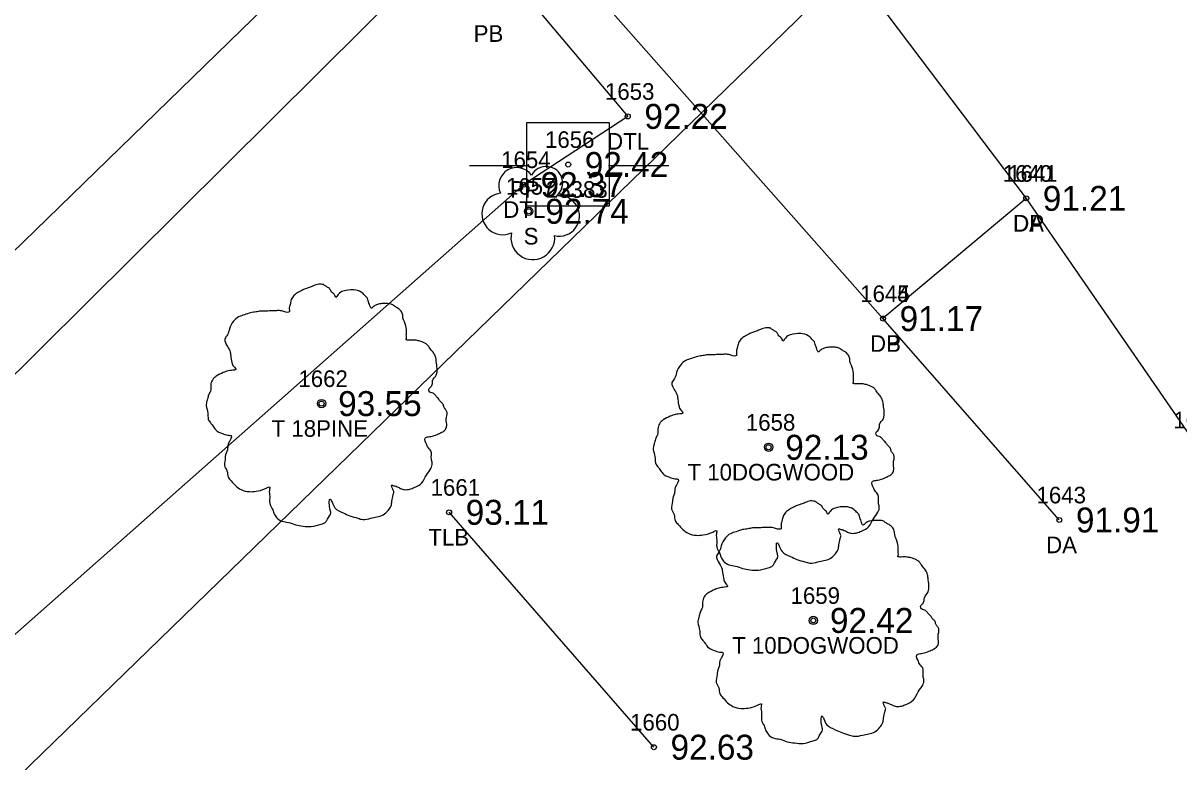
# Model space of a CAD drawing. Extents: x 2500794 to 2511032, y 910653 to 917533.
# Drawn here: x 2504774.7 to 2504844.2, y 912430.5 to 912475 of the extents above; entities that cross this region are included whole.
import ezdxf

# ---------------------------------------------------------------- set-up
doc = ezdxf.new("R2010")
doc.units = 0
for name, color, linetype in [('RD_EX_DR_Pipe_txCode', 7, 'Continuous'), ('RD_EX_Driveway', 7, 'Continuous'), ('RD_EX_Driveway_txCode', 7, 'Continuous'), ('RD_EX_H2O_txCode', 7, 'Continuous'), ('RD_EX_Road', 7, 'Continuous'), ('RD_EX_RW', 7, 'Continuous'), ('RD_EX_TX_Driveway_ELEV', 7, 'Continuous'), ('RD_EX_TX_H2O_ELEV', 7, 'Continuous'), ('RD_EX_TX_VEG_ELEV', 7, 'Continuous'), ('RD_EX_UT', 7, 'Continuous'), ('RD_EX_UT_txCode', 7, 'Continuous'), ('RD_EX_VEG', 7, 'Continuous'), ('RD_EX_VEG_txCode', 7, 'Continuous'), ('RD_HC_Survey_ELEV', 7, 'Continuous'), ('RD_SMD_Locator', 7, 'Continuous')]:
    doc.layers.add(name, color=color, linetype=linetype)

msp = doc.modelspace()

# ---------------------------------------------------------------- linework, layer by layer
at = {"layer": 'RD_EX_Driveway'}
for p, q in [((2504835.044, 912464.414), (2504845.262, 912449.566)), ((2504837.037, 912445.051), (2504826.429, 912457.175))]:
    msp.add_line(p, q, dxfattribs=at)
msp.add_lwpolyline([(2504810.704, 912496.654), (2504835.044, 912464.414), (2504826.429, 912457.175), (2504806.818, 912479.369), (2504795.802, 912482.321)], dxfattribs=at)
at = {"layer": 'RD_EX_H2O_txCode'}
for points in [[(2504800.806, 912480.276), (2504750.663, 912430.459), (2504704.437, 912384.367), (2504708.299, 912378.983)], [(2504800.806, 912480.276), (2504804.552, 912477.095), (2504811.074, 912469.349), (2504804.829, 912465.241), (2504757.76, 912423.62), (2504708.299, 912378.983)]]:
    msp.add_lwpolyline(points, dxfattribs=at)
at = {"layer": 'RD_EX_Road'}
msp.add_lwpolyline([(2505370.603, 913041.775), (2505311.868, 912984.114), (2505268.008, 912941.433), (2505190.916, 912867.207), (2505116.283, 912794.427), (2505039.137, 912719.026), (2504973.125, 912654.769), (2504957.318, 912639.487), (2504897.436, 912581.224), (2504858.984, 912543.75), (2504838.286, 912523.698), (2504810.704, 912496.654), (2504795.802, 912482.321), (2504747.074, 912434.903), (2504696.605, 912386.172), (2504686.806, 912376.673), (2504668.39, 912358.371), (2504598.363, 912290.291), (2504547.084, 912240.341)], dxfattribs=at)
at = {"layer": 'RD_EX_RW'}
msp.add_line((2503981.182, 911658.034), (2505252.676, 912894.806), dxfattribs=at)
at = {"layer": 'RD_EX_UT'}
for p, q in [((2504809.981, 912468.96), (2504804.981, 912468.96)), ((2504804.981, 912468.96), (2504804.981, 912463.96)), ((2504809.981, 912463.96), (2504809.981, 912468.96)), ((2504801.55, 912466.398), (2504805.019, 912466.398)), ((2504809.91, 912466.398), (2504813.55, 912466.398)), ((2504804.981, 912463.96), (2504809.981, 912463.96))]:
    msp.add_line(p, q, dxfattribs=at)
at = {"layer": 'RD_EX_VEG'}
msp.add_line((2504812.648, 912431.372), (2504800.324, 912445.513), dxfattribs=at)
for centre, radius in [((2504805.118, 912463.636), 0.25), ((2504792.654, 912452.058), 0.25), ((2504792.642, 912452.039), 0.0001), ((2504819.549, 912449.429), 0.25), ((2504819.537, 912449.41), 0.0001), ((2504822.238, 912439.002), 0.25), ((2504822.226, 912438.983), 0.0001)]:
    msp.add_circle(centre, radius, dxfattribs=at)
for centre, radius, start, end in [((2504804.397, 912465.183), 1.084, 34.97629, 204.75602), ((2504806.164, 912465.338), 0.995, 308.76261, 152.04674), ((2504803.555, 912463.481), 1.257, 96.45179, 294.73401), ((2504806.958, 912463.357), 1.218, 256.56668, 98.10463), ((2504805.364, 912462.04), 1.318, 166.88266, 5.75893)]:
    msp.add_arc(centre, radius, start, end, dxfattribs=at)
for points in [[(2504792.786, 912459.225), (2504792.486, 912459.25), (2504792.162, 912459.15), (2504791.912, 912459.05), (2504791.687, 912458.975), (2504791.462, 912458.875), (2504791.162, 912458.701), (2504790.937, 912458.501), (2504790.812, 912458.251), (2504790.762, 912458.026), (2504790.712, 912457.751), (2504790.712, 912457.576), (2504790.587, 912457.551), (2504790.437, 912457.576), (2504790.187, 912457.651), (2504789.938, 912457.651), (2504789.688, 912457.651), (2504789.338, 912457.626), (2504788.988, 912457.626), (2504788.713, 912457.576), (2504788.388, 912457.526), (2504788.013, 912457.401), (2504787.664, 912457.276), (2504787.364, 912457.026), (2504787.114, 912456.551), (2504786.989, 912456.202), (2504786.839, 912455.952), (2504786.989, 912455.502), (2504787.164, 912455.152), (2504787.189, 912454.952), (2504787.264, 912454.527), (2504787.364, 912454.302), (2504787.489, 912454.102), (2504787.414, 912454.078), (2504787.039, 912454.028), (2504786.739, 912453.928), (2504786.314, 912453.703), (2504786.089, 912453.478), (2504785.989, 912453.153), (2504785.964, 912452.803), (2504785.864, 912452.603), (2504785.789, 912452.328), (2504785.764, 912452.253), (2504785.714, 912451.928), (2504785.814, 912451.479), (2504785.839, 912451.129), (2504785.964, 912450.904), (2504786.114, 912450.729), (2504786.289, 912450.479), (2504786.689, 912450.254), (2504787.014, 912450.154), (2504787.214, 912450.129), (2504787.039, 912449.629), (2504786.989, 912449.28), (2504786.864, 912448.88), (2504786.864, 912448.805), (2504786.814, 912448.33), (2504786.964, 912448.005), (2504787.039, 912447.63), (2504787.214, 912447.405), (2504787.489, 912447.106), (2504787.813, 912446.881), (2504788.313, 912446.756), (2504788.713, 912446.781), (2504789.288, 912446.956), (2504789.538, 912447.031), (2504789.513, 912446.856), (2504789.538, 912446.481), (2504789.538, 912446.056), (2504789.688, 912445.731), (2504789.788, 912445.456), (2504789.938, 912445.206), (2504790.262, 912444.982), (2504790.662, 912444.907), (2504791.087, 912444.757), (2504791.537, 912444.682), (2504792.037, 912444.657), (2504792.636, 912444.807), (2504792.911, 912444.932), (2504793.011, 912445.106), (2504793.211, 912445.481), (2504793.161, 912445.706), (2504793.186, 912446.306), (2504793.286, 912446.131), (2504793.461, 912445.781), (2504793.961, 912445.481), (2504794.361, 912445.306), (2504794.835, 912445.156), (2504795.135, 912445.081), (2504795.61, 912445.156), (2504795.985, 912445.231), (2504796.36, 912445.356), (2504796.66, 912445.631), (2504796.835, 912445.906), (2504796.885, 912446.181), (2504796.959, 912446.556), (2504797.009, 912446.731)], [(2504797.009, 912446.731), (2504796.935, 912446.906), (2504796.885, 912447.156), (2504796.959, 912447.131), (2504797.134, 912447.081), (2504797.409, 912446.956), (2504797.634, 912446.881), (2504797.959, 912446.906), (2504798.234, 912447.006), (2504798.684, 912447.281), (2504798.959, 912447.755), (2504799.233, 912448.155), (2504799.308, 912448.48), (2504799.258, 912448.705), (2504799.233, 912449.205), (2504799.034, 912449.455), (2504798.984, 912449.579), (2504798.884, 912449.979), (2504798.959, 912450.029), (2504799.233, 912450.079), (2504799.608, 912450.204), (2504799.883, 912450.329), (2504800.108, 912450.504), (2504800.183, 912450.729), (2504800.158, 912451.129), (2504800.208, 912451.529), (2504800.133, 912451.679), (2504800.033, 912451.828), (2504799.958, 912452.028), (2504799.808, 912452.178), (2504799.708, 912452.328), (2504799.608, 912452.428), (2504799.483, 912452.578), (2504799.308, 912452.703), (2504799.159, 912452.753), (2504799.109, 912452.903), (2504799.258, 912453.103), (2504799.308, 912453.203), (2504799.333, 912453.428), (2504799.558, 912453.778), (2504799.608, 912454.177), (2504799.558, 912454.602), (2504799.508, 912454.877), (2504799.358, 912455.152), (2504799.159, 912455.402), (2504799.034, 912455.577), (2504798.859, 912455.702), (2504798.534, 912455.827), (2504798.284, 912455.877), (2504797.934, 912455.877), (2504797.734, 912455.927), (2504797.759, 912455.977), (2504797.759, 912456.127), (2504797.759, 912456.402), (2504797.684, 912456.851), (2504797.534, 912457.351), (2504797.534, 912457.376), (2504797.434, 912457.626), (2504797.209, 912457.826), (2504797.034, 912457.926), (2504796.835, 912458.051), (2504796.585, 912458.076), (2504796.285, 912458.076), (2504796.01, 912458.026), (2504795.81, 912457.926), (2504795.635, 912457.801), (2504795.56, 912457.951), (2504795.46, 912458.251), (2504795.41, 912458.401), (2504795.26, 912458.576), (2504795.035, 912458.775), (2504794.585, 912458.9), (2504793.961, 912458.825), (2504793.661, 912458.626), (2504793.511, 912458.451), (2504793.461, 912458.576), (2504793.261, 912458.775), (2504793.161, 912458.95), (2504792.986, 912459.075), (2504792.836, 912459.175), (2504792.736, 912459.225)], [(2504819.681, 912456.597), (2504819.381, 912456.622), (2504819.057, 912456.522), (2504818.807, 912456.422), (2504818.582, 912456.347), (2504818.357, 912456.247), (2504818.057, 912456.072), (2504817.832, 912455.872), (2504817.707, 912455.622), (2504817.657, 912455.397), (2504817.607, 912455.122), (2504817.607, 912454.947), (2504817.482, 912454.922), (2504817.332, 912454.947), (2504817.082, 912455.022), (2504816.833, 912455.022), (2504816.583, 912455.022), (2504816.233, 912454.997), (2504815.883, 912454.997), (2504815.608, 912454.947), (2504815.283, 912454.897), (2504814.908, 912454.772), (2504814.559, 912454.647), (2504814.259, 912454.397), (2504814.009, 912453.923), (2504813.884, 912453.573), (2504813.734, 912453.323), (2504813.884, 912452.873), (2504814.059, 912452.523), (2504814.084, 912452.323), (2504814.159, 912451.899), (2504814.259, 912451.674), (2504814.384, 912451.474), (2504814.309, 912451.449), (2504813.934, 912451.399), (2504813.634, 912451.299), (2504813.209, 912451.074), (2504812.984, 912450.849), (2504812.884, 912450.524), (2504812.859, 912450.174), (2504812.759, 912449.974), (2504812.684, 912449.7), (2504812.659, 912449.625), (2504812.609, 912449.3), (2504812.709, 912448.85), (2504812.734, 912448.5), (2504812.859, 912448.275), (2504813.009, 912448.1), (2504813.184, 912447.85), (2504813.584, 912447.625), (2504813.909, 912447.525), (2504814.109, 912447.501), (2504813.934, 912447.001), (2504813.884, 912446.651), (2504813.759, 912446.251), (2504813.759, 912446.176), (2504813.709, 912445.701), (2504813.859, 912445.376), (2504813.934, 912445.002), (2504814.109, 912444.777), (2504814.384, 912444.477), (2504814.708, 912444.252), (2504815.208, 912444.127), (2504815.608, 912444.152), (2504816.183, 912444.327), (2504816.433, 912444.402), (2504816.408, 912444.227), (2504816.433, 912443.852), (2504816.433, 912443.427), (2504816.583, 912443.102), (2504816.683, 912442.828), (2504816.833, 912442.578), (2504817.157, 912442.353), (2504817.557, 912442.278), (2504817.982, 912442.128), (2504818.432, 912442.053), (2504818.932, 912442.028), (2504819.531, 912442.178), (2504819.806, 912442.303), (2504819.906, 912442.478), (2504820.106, 912442.853), (2504820.056, 912443.077), (2504820.081, 912443.677), (2504820.181, 912443.502), (2504820.356, 912443.152), (2504820.856, 912442.853), (2504821.256, 912442.678), (2504821.73, 912442.528), (2504822.03, 912442.453), (2504822.505, 912442.528), (2504822.88, 912442.603), (2504823.255, 912442.728), (2504823.555, 912443.002), (2504823.73, 912443.277), (2504823.78, 912443.552), (2504823.854, 912443.927), (2504823.904, 912444.102)], [(2504823.904, 912444.102), (2504823.83, 912444.277), (2504823.78, 912444.527), (2504823.854, 912444.502), (2504824.029, 912444.452), (2504824.304, 912444.327), (2504824.529, 912444.252), (2504824.854, 912444.277), (2504825.129, 912444.377), (2504825.579, 912444.652), (2504825.854, 912445.127), (2504826.128, 912445.526), (2504826.203, 912445.851), (2504826.153, 912446.076), (2504826.128, 912446.576), (2504825.929, 912446.826), (2504825.879, 912446.951), (2504825.779, 912447.351), (2504825.854, 912447.401), (2504826.128, 912447.451), (2504826.503, 912447.575), (2504826.778, 912447.7), (2504827.003, 912447.875), (2504827.078, 912448.1), (2504827.053, 912448.5), (2504827.103, 912448.9), (2504827.028, 912449.05), (2504826.928, 912449.2), (2504826.853, 912449.4), (2504826.703, 912449.55), (2504826.603, 912449.7), (2504826.503, 912449.799), (2504826.378, 912449.949), (2504826.203, 912450.074), (2504826.054, 912450.124), (2504826.004, 912450.274), (2504826.153, 912450.474), (2504826.203, 912450.574), (2504826.228, 912450.799), (2504826.453, 912451.149), (2504826.503, 912451.549), (2504826.453, 912451.974), (2504826.403, 912452.248), (2504826.253, 912452.523), (2504826.054, 912452.773), (2504825.929, 912452.948), (2504825.754, 912453.073), (2504825.429, 912453.198), (2504825.179, 912453.248), (2504824.829, 912453.248), (2504824.629, 912453.298), (2504824.654, 912453.348), (2504824.654, 912453.498), (2504824.654, 912453.773), (2504824.579, 912454.223), (2504824.429, 912454.722), (2504824.429, 912454.747), (2504824.329, 912454.997), (2504824.104, 912455.197), (2504823.929, 912455.297), (2504823.73, 912455.422), (2504823.48, 912455.447), (2504823.18, 912455.447), (2504822.905, 912455.397), (2504822.705, 912455.297), (2504822.53, 912455.172), (2504822.455, 912455.322), (2504822.355, 912455.622), (2504822.305, 912455.772), (2504822.155, 912455.947), (2504821.93, 912456.147), (2504821.48, 912456.272), (2504820.856, 912456.197), (2504820.556, 912455.997), (2504820.406, 912455.822), (2504820.356, 912455.947), (2504820.156, 912456.147), (2504820.056, 912456.322), (2504819.881, 912456.447), (2504819.731, 912456.547), (2504819.631, 912456.597)], [(2504822.37, 912446.169), (2504822.07, 912446.194), (2504821.745, 912446.094), (2504821.496, 912445.995), (2504821.271, 912445.92), (2504821.046, 912445.82), (2504820.746, 912445.645), (2504820.521, 912445.445), (2504820.396, 912445.195), (2504820.346, 912444.97), (2504820.296, 912444.695), (2504820.296, 912444.52), (2504820.171, 912444.495), (2504820.021, 912444.52), (2504819.771, 912444.595), (2504819.521, 912444.595), (2504819.271, 912444.595), (2504818.922, 912444.57), (2504818.572, 912444.57), (2504818.297, 912444.52), (2504817.972, 912444.47), (2504817.597, 912444.345), (2504817.247, 912444.22), (2504816.948, 912443.97), (2504816.698, 912443.496), (2504816.573, 912443.146), (2504816.423, 912442.896), (2504816.573, 912442.446), (2504816.748, 912442.096), (2504816.773, 912441.896), (2504816.848, 912441.472), (2504816.948, 912441.247), (2504817.072, 912441.047), (2504816.998, 912441.022), (2504816.623, 912440.972), (2504816.323, 912440.872), (2504815.898, 912440.647), (2504815.673, 912440.422), (2504815.573, 912440.097), (2504815.548, 912439.747), (2504815.448, 912439.547), (2504815.373, 912439.272), (2504815.348, 912439.197), (2504815.298, 912438.873), (2504815.398, 912438.423), (2504815.423, 912438.073), (2504815.548, 912437.848), (2504815.698, 912437.673), (2504815.873, 912437.423), (2504816.273, 912437.198), (2504816.598, 912437.098), (2504816.798, 912437.073), (2504816.623, 912436.574), (2504816.573, 912436.224), (2504816.448, 912435.824), (2504816.448, 912435.749), (2504816.398, 912435.274), (2504816.548, 912434.949), (2504816.623, 912434.575), (2504816.798, 912434.35), (2504817.072, 912434.05), (2504817.397, 912433.825), (2504817.897, 912433.7), (2504818.297, 912433.725), (2504818.872, 912433.9), (2504819.122, 912433.975), (2504819.097, 912433.8), (2504819.122, 912433.425), (2504819.122, 912433), (2504819.271, 912432.675), (2504819.371, 912432.4), (2504819.521, 912432.151), (2504819.846, 912431.926), (2504820.246, 912431.851), (2504820.671, 912431.701), (2504821.121, 912431.626), (2504821.62, 912431.601), (2504822.22, 912431.751), (2504822.495, 912431.876), (2504822.595, 912432.051), (2504822.795, 912432.425), (2504822.745, 912432.65), (2504822.77, 912433.25), (2504822.87, 912433.075), (2504823.045, 912432.725), (2504823.545, 912432.425), (2504823.944, 912432.251), (2504824.419, 912432.101), (2504824.719, 912432.026), (2504825.194, 912432.101), (2504825.569, 912432.176), (2504825.944, 912432.301), (2504826.243, 912432.575), (2504826.418, 912432.85), (2504826.468, 912433.125), (2504826.543, 912433.5), (2504826.593, 912433.675)], [(2504826.593, 912433.675), (2504826.518, 912433.85), (2504826.468, 912434.1), (2504826.543, 912434.075), (2504826.718, 912434.025), (2504826.993, 912433.9), (2504827.218, 912433.825), (2504827.543, 912433.85), (2504827.818, 912433.95), (2504828.268, 912434.225), (2504828.542, 912434.699), (2504828.817, 912435.099), (2504828.892, 912435.424), (2504828.842, 912435.649), (2504828.817, 912436.149), (2504828.617, 912436.399), (2504828.567, 912436.524), (2504828.467, 912436.923), (2504828.542, 912436.973), (2504828.817, 912437.023), (2504829.192, 912437.148), (2504829.467, 912437.273), (2504829.692, 912437.448), (2504829.767, 912437.673), (2504829.742, 912438.073), (2504829.792, 912438.473), (2504829.717, 912438.623), (2504829.617, 912438.773), (2504829.542, 912438.973), (2504829.392, 912439.122), (2504829.292, 912439.272), (2504829.192, 912439.372), (2504829.067, 912439.522), (2504828.892, 912439.647), (2504828.742, 912439.697), (2504828.692, 912439.847), (2504828.842, 912440.047), (2504828.892, 912440.147), (2504828.917, 912440.372), (2504829.142, 912440.722), (2504829.192, 912441.122), (2504829.142, 912441.546), (2504829.092, 912441.821), (2504828.942, 912442.096), (2504828.742, 912442.346), (2504828.617, 912442.521), (2504828.442, 912442.646), (2504828.118, 912442.771), (2504827.868, 912442.821), (2504827.518, 912442.821), (2504827.318, 912442.871), (2504827.343, 912442.921), (2504827.343, 912443.071), (2504827.343, 912443.346), (2504827.268, 912443.795), (2504827.118, 912444.295), (2504827.118, 912444.32), (2504827.018, 912444.57), (2504826.793, 912444.77), (2504826.618, 912444.87), (2504826.418, 912444.995), (2504826.168, 912445.02), (2504825.869, 912445.02), (2504825.594, 912444.97), (2504825.394, 912444.87), (2504825.219, 912444.745), (2504825.144, 912444.895), (2504825.044, 912445.195), (2504824.994, 912445.345), (2504824.844, 912445.52), (2504824.619, 912445.72), (2504824.169, 912445.845), (2504823.545, 912445.77), (2504823.245, 912445.57), (2504823.095, 912445.395), (2504823.045, 912445.52), (2504822.845, 912445.72), (2504822.745, 912445.895), (2504822.57, 912446.02), (2504822.42, 912446.119), (2504822.32, 912446.169)]]:
    msp.add_spline(points, degree=3, dxfattribs=at)
at = {"layer": 'RD_SMD_Locator'}
for centre in [(2504811.074, 912469.349), (2504807.49, 912466.451), (2504804.829, 912465.241), (2504835.044, 912464.414), (2504835.044, 912464.414), (2504805.118, 912463.636), (2504826.429, 912457.175), (2504826.429, 912457.175), (2504792.654, 912452.058), (2504819.549, 912449.429), (2504800.324, 912445.513), (2504837.037, 912445.051), (2504822.238, 912439.002), (2504812.648, 912431.372)]:
    msp.add_circle(centre, 0.15, dxfattribs=at)

# ---------------------------------------------------------------- texts
at = {"layer": 'RD_EX_DR_Pipe_txCode'}
msp.add_text('PB', height=1, dxfattribs=at).set_placement((2504801.804, 912473.838))
at = {"layer": 'RD_EX_Driveway_txCode'}
for s, p in [('1640', (2504833.635, 912465.414)), ('1641', (2504833.958, 912465.414)), ('DA', (2504834.249, 912462.414)), ('DP', (2504834.265, 912462.414)), ('1644', (2504825.059, 912458.175)), ('1645', (2504825.059, 912458.175)), ('DB', (2504825.649, 912455.175)), ('DP', (2504825.649, 912455.175)), ('1642', (2504843.892, 912450.566)), ('1643', (2504835.667, 912446.051)), ('DA', (2504836.242, 912443.051))]:
    msp.add_text(s, height=1, dxfattribs=at).set_placement(p)
at = {"layer": 'RD_EX_H2O_txCode'}
for s, p in [('1653', (2504809.704, 912470.349)), ('DTL', (2504809.83, 912467.349)), ('1654', (2504803.459, 912466.241)), ('DTL', (2504803.585, 912463.241))]:
    msp.add_text(s, height=1, dxfattribs=at).set_placement(p)
at = {"layer": 'RD_EX_TX_Driveway_ELEV'}
for s, p in [('91.21', (2504836.044, 912463.664)), ('91.21', (2504836.044, 912463.664)), ('91.17', (2504827.429, 912456.425)), ('91.17', (2504827.429, 912456.425)), ('91.91', (2504838.037, 912444.301))]:
    msp.add_text(s, height=1.5, dxfattribs=at).set_placement(p)
at = {"layer": 'RD_EX_TX_H2O_ELEV'}
for s, p in [('92.22', (2504812.074, 912468.599)), ('92.37', (2504805.829, 912464.491))]:
    msp.add_text(s, height=1.5, dxfattribs=at).set_placement(p)
at = {"layer": 'RD_EX_TX_VEG_ELEV'}
for s, p in [('92.74', (2504806.118, 912462.886)), ('93.55', (2504793.654, 912451.308)), ('92.13', (2504820.549, 912448.679)), ('93.11', (2504801.324, 912444.763)), ('92.42', (2504823.238, 912438.252)), ('92.63', (2504813.648, 912430.622))]:
    msp.add_text(s, height=1.5, dxfattribs=at).set_placement(p)
at = {"layer": 'RD_EX_UT_txCode'}
for s, p in [('1656', (2504806.097, 912467.451)), ('PP 23383', (2504803.994, 912464.451))]:
    msp.add_text(s, height=1, dxfattribs=at).set_placement(p)
at = {"layer": 'RD_EX_VEG_txCode'}
for s, p in [('1657', (2504803.748, 912464.636)), ('S', (2504804.811, 912461.636)), ('1662', (2504791.261, 912453.058)), ('1658', (2504818.179, 912450.429)), ('T 18PINE', (2504789.65, 912450.058)), ('T 10DOGWOOD', (2504814.668, 912447.429)), ('1661', (2504799.214, 912446.513)), ('TLB', (2504799.08, 912443.513)), ('1659', (2504820.868, 912440.002)), ('T 10DOGWOOD', (2504817.356, 912437.002)), ('1660', (2504811.215, 912432.372))]:
    msp.add_text(s, height=1, dxfattribs=at).set_placement(p)
at = {"layer": 'RD_HC_Survey_ELEV'}
msp.add_text('92.42', height=1.5, dxfattribs=at).set_placement((2504808.49, 912465.701))

doc.saveas('drawing.dxf')
